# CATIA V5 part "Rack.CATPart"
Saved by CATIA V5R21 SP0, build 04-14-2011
Part number: Part2
Bounding box of the stored display mesh (mm): x -50 to 50, y -20 to 20, z 14.357 to 70
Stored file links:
  D:\CATIA V5R21 E-RESOURCES\CATIA-V5R21\catia-v5r21-Prts\c16_catia_v5r21_prt\Rack Joint(Fig16-57)\Rack.CATPart
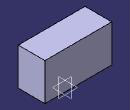
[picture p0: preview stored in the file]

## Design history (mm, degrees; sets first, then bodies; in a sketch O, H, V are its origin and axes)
Body1 (main body)
  Sketch1 on yz-plane, origin (0, 0, 0), H (0, 1, 0), V (0, 0, 1)
    point P1 (20, 30)
    line L1 (-20, 14.3569) -> (20, 14.3569)
    point P2 (-20, 14.3569)
    point P3 (20, 14.3569)
    reference intersected line E1 through (0, 0) direction (-1, 0) from xy-plane
    reference intersected line E3 through (0, 0) direction (0, 1) from zx-plane
    reference intersected line E4 through (0, 0) direction (-1, 0) from xy-plane
    reference intersected line E6 through (0, 0) direction (0, 1) from zx-plane
    line L2 (20, 14.3569) -> (20, 70)
    point P4 (20, 70)
    line L3 (20, 70) -> (-20, 70)
    point P5 (-20, 70)
    line L4 (-20, 14.3569) -> (-20, 70)
    reference intersected line E7 through (0, 0) direction (-1, 0) from xy-plane
    reference intersected line E9 through (0, 0) direction (0, 1) from zx-plane
    distance E1 L1 = 14.3569
    distance P2 E3 = 20
    distance P1 P3 = 15.6431
    distance H L3 = 70
    distance P4 P5 = 40
    horizontal: L1 H, E1 H, E4 H, L3 H, E7 H
    vertical: E3 V, E6 V, L2 V, L4 V, E9 V
    perpendicularity: E7 L2
    coincidence: P1 L2
  Pad1: profile Sketch1, direction (1, 0, 0), length 50, mirrored extent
